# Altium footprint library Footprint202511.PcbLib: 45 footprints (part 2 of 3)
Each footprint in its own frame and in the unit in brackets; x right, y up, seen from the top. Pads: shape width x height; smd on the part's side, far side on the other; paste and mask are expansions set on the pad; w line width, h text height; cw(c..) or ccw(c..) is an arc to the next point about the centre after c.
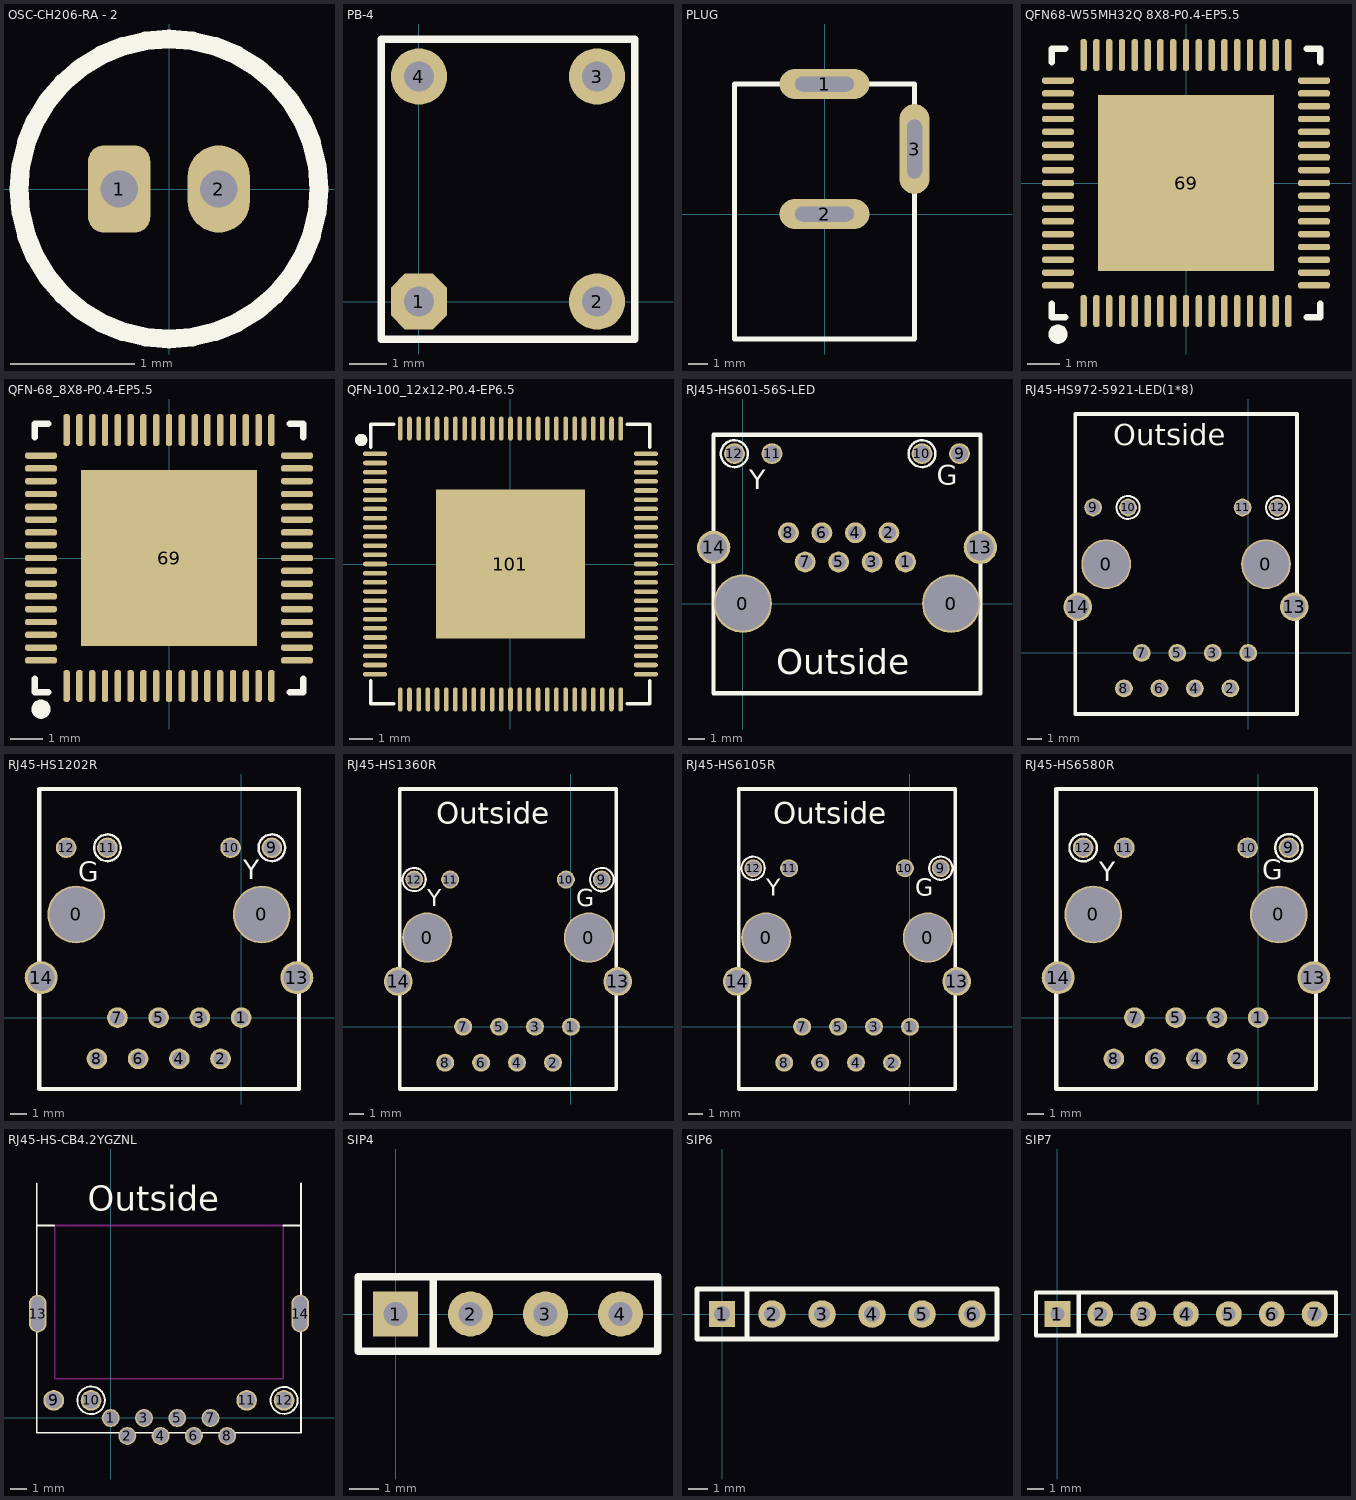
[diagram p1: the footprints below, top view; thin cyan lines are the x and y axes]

## OSC-CH206-RA - 2 [mm]
height 3.9
pads (2):
  rrect50% 0.5x0.7 hole 0.3: 1(-0.4,0)
  oval 0.5x0.7 hole 0.3: 2(0.4,0)
Top Overlay:
  circle w0.15: c0,0 r1.205

## PB-4 [mil]
height 21.65
pads (4):
  oct 60x60 hole 32: 1(0,0)
  round 60 hole 32: 2(190,0) 3(190,240) 4(0,240)
Top Overlay:
  lines w8: -40,-40 230,-40 230,280 -40,280 -40,-40

## PLUG [mil]
pads (3):
  oval 180x60 hole 30 slot 118.11 at 0 deg: 1(0,260) 2(0,0)
  oval 60x180 hole 30 slot 118.11 at 90 deg: 3(180,130)
Top Overlay:
  lines w10: -180,-250 180,-250 180,260 -180,260 -180,-250

## QFN68-W55MH32Q 8X8-P0.4-EP5.5 [mm]
height 1.45
pads (69):
  rrect80% 0.2x1 smd mask+0.051: 1(-3.2,-4) 2(-2.8,-4) 3(-2.4,-4) 4(-2,-4) 5(-1.6,-4) 6(-1.2,-4) 7(-0.8,-4) 8(-0.4,-4) 9(0,-4) 10(0.4,-4) 11(0.8,-4) 12(1.2,-4) 13(1.6,-4) 14(2,-4) 15(2.4,-4) 16(2.8,-4) 17(3.2,-4) 35(3.2,4) 36(2.8,4) 37(2.4,4) 38(2,4) 39(1.6,4) 40(1.2,4) 41(0.8,4) 42(0.4,4) 43(0,4) 44(-0.4,4) 45(-0.8,4) 46(-1.2,4) 47(-1.6,4) 48(-2,4) 49(-2.4,4) 50(-2.8,4) 51(-3.2,4)
  rrect80% 1x0.2 smd mask+0.051: 18(4,-3.2) 19(4,-2.8) 20(4,-2.4) 21(4,-2) 22(4,-1.6) 23(4,-1.2) 24(4,-0.8) 25(4,-0.4) 26(4,0) 27(4,0.4) 28(4,0.8) 29(4,1.2) 30(4,1.6) 31(4,2) 32(4,2.4) 33(4,2.8) 34(4,3.2) 52(-4,3.2) 53(-4,2.8) 54(-4,2.4) 55(-4,2) 56(-4,1.6) 57(-4,1.2) 58(-4,0.8) 59(-4,0.4) 60(-4,0) 61(-4,-0.4) 62(-4,-0.8) 63(-4,-1.2) 64(-4,-1.6) 65(-4,-2) 66(-4,-2.4) 67(-4,-2.8) 68(-4,-3.2)
  rect 5.5x5.5 smd paste-100 mask+0.051: 69(0,0)
Top Overlay:
  lines w0.2: -4.2,-3.775 -4.2,-4.2 -3.775,-4.2 ; -4.2,3.775 -4.2,4.2 -3.775,4.2 ; 3.775,-4.2 4.2,-4.2 4.2,-3.775 ; 3.775,4.2 4.2,4.2 4.2,3.775
  lines w0.3: -4,-4.575 ccw(c-3.999,-4.725) -3.999,-4.875 ccw(c-3.999,-4.725) -3.998,-4.575
3D body: height 1.05, standoff 0, extent -7.999,-7.999 8.001,8.001

## QFN-68_8X8-P0.4-EP5.5 [mm]
pads (69):
  rrect80% 0.2x1 smd mask+0.051: 1(-3.2,-4) 2(-2.8,-4) 3(-2.4,-4) 4(-2,-4) 5(-1.6,-4) 6(-1.2,-4) 7(-0.8,-4) 8(-0.4,-4) 9(0,-4) 10(0.4,-4) 11(0.8,-4) 12(1.2,-4) 13(1.6,-4) 14(2,-4) 15(2.4,-4) 16(2.8,-4) 17(3.2,-4) 35(3.2,4) 36(2.8,4) 37(2.4,4) 38(2,4) 39(1.6,4) 40(1.2,4) 41(0.8,4) 42(0.4,4) 43(0,4) 44(-0.4,4) 45(-0.8,4) 46(-1.2,4) 47(-1.6,4) 48(-2,4) 49(-2.4,4) 50(-2.8,4) 51(-3.2,4)
  rrect80% 1x0.2 smd mask+0.051: 18(4,-3.2) 19(4,-2.8) 20(4,-2.4) 21(4,-2) 22(4,-1.6) 23(4,-1.2) 24(4,-0.8) 25(4,-0.4) 26(4,0) 27(4,0.4) 28(4,0.8) 29(4,1.2) 30(4,1.6) 31(4,2) 32(4,2.4) 33(4,2.8) 34(4,3.2) 52(-4,3.2) 53(-4,2.8) 54(-4,2.4) 55(-4,2) 56(-4,1.6) 57(-4,1.2) 58(-4,0.8) 59(-4,0.4) 60(-4,0) 61(-4,-0.4) 62(-4,-0.8) 63(-4,-1.2) 64(-4,-1.6) 65(-4,-2) 66(-4,-2.4) 67(-4,-2.8) 68(-4,-3.2)
  rect 5.5x5.5 smd paste-100 mask+0.051: 69(0,0)
Top Overlay:
  lines w0.2: -4.2,-3.775 -4.2,-4.2 -3.775,-4.2 ; -4.2,3.775 -4.2,4.2 -3.775,4.2 ; 3.775,-4.2 4.2,-4.2 4.2,-3.775 ; 3.775,4.2 4.2,4.2 4.2,3.775
  lines w0.3: -4,-4.575 ccw(c-3.999,-4.725) -3.999,-4.875 ccw(c-3.999,-4.725) -3.998,-4.575
3D body: height 1.05, standoff 0, extent -7.999,-7.999 8.001,8.001

## QFN-100_12x12-P0.4-EP6.5 [mm]
pads (101):
  oval 1.05x0.2 smd mask+0.051: 1(-5.9,4.8) 2(-5.9,4.4) 3(-5.9,4) 4(-5.9,3.6) 5(-5.9,3.2) 6(-5.9,2.8) 7(-5.9,2.4) 8(-5.9,2) 9(-5.9,1.6) 10(-5.9,1.2) 11(-5.9,0.8) 12(-5.9,0.4) 13(-5.9,0) 14(-5.9,-0.4) 15(-5.9,-0.8) 16(-5.9,-1.2) 17(-5.9,-1.6) 18(-5.9,-2) 19(-5.9,-2.4) 20(-5.9,-2.8) 21(-5.9,-3.2) 22(-5.9,-3.6) 23(-5.9,-4) 24(-5.9,-4.4) 25(-5.9,-4.8) 51(5.9,-4.8) 52(5.9,-4.4) 53(5.9,-4) 54(5.9,-3.6) 55(5.9,-3.2) 56(5.9,-2.8) 57(5.9,-2.4) 58(5.9,-2) 59(5.9,-1.6) 60(5.9,-1.2) 61(5.9,-0.8) 62(5.9,-0.4) 63(5.9,0) 64(5.9,0.4) 65(5.9,0.8) 66(5.9,1.2) 67(5.9,1.6) 68(5.9,2) 69(5.9,2.4) 70(5.9,2.8) 71(5.9,3.2) 72(5.9,3.6) 73(5.9,4) 74(5.9,4.4) 75(5.9,4.8)
  oval 0.2x1.05 smd mask+0.051: 26(-4.8,-5.9) 27(-4.4,-5.9) 28(-4,-5.9) 29(-3.6,-5.9) 30(-3.2,-5.9) 31(-2.8,-5.9) 32(-2.4,-5.9) 33(-2,-5.9) 34(-1.6,-5.9) 35(-1.2,-5.9) 36(-0.8,-5.9) 37(-0.4,-5.9) 38(0,-5.9) 39(0.4,-5.9) 40(0.8,-5.9) 41(1.2,-5.9) 42(1.6,-5.9) 43(2,-5.9) 44(2.4,-5.9) 45(2.8,-5.9) 46(3.2,-5.9) 47(3.6,-5.9) 48(4,-5.9) 49(4.4,-5.9) 50(4.8,-5.9) 76(4.8,5.9) 77(4.4,5.9) 78(4,5.9) 79(3.6,5.9) 80(3.2,5.9) 81(2.8,5.9) 82(2.4,5.9) 83(2,5.9) 84(1.6,5.9) 85(1.2,5.9) 86(0.8,5.9) 87(0.4,5.9) 88(0,5.9) 89(-0.4,5.9) 90(-0.8,5.9) 91(-1.2,5.9) 92(-1.6,5.9) 93(-2,5.9) 94(-2.4,5.9) 95(-2.8,5.9) 96(-3.2,5.9) 97(-3.6,5.9) 98(-4,5.9) 99(-4.4,5.9) 100(-4.8,5.9)
  rect 6.5x6.5 smd mask+0.051: 101(0,0)
Top Overlay:
  circle w0.254: c-6.5,5.4 r0.141
  lines w0.152: -6.076,-5.076 -6.076,-6.076 -5.076,-6.076 ; -6.076,5.076 -6.076,6.076 -5.076,6.076 ; 5.076,-6.076 6.076,-6.076 6.076,-5.076 ; 5.076,6.076 6.076,6.076 6.076,5.076
3D body: height 0.9, standoff 0, extent -6,-6 6.02,6.02

## RJ45-HS601-56S-LED [mm]
height 13.2
pads (16):
  round 3.556 hole 3.302: 0(0,0) 0(12.7,0)
  round 1.27 hole 0.889: 1(9.92,2.54) 2(8.9,4.32) 3(7.88,2.54) 4(6.86,4.32) 5(5.84,2.54) 6(4.82,4.32) 7(3.8,2.54) 8(2.78,4.32)
  round 1.27 hole 1.016: 9(13.21,9.14) 10(10.92,9.14) 11(1.78,9.14) 12(-0.51,9.14)
  round 2.032 hole 1.626: 13(14.475,3.43)
  round 2.032 hole 1.651: 14(-1.775,3.43)
Top Overlay:
  circle w0.15: c-0.514,9.14 r0.82
  circle w0.15: c10.92,9.14 r0.82
  lines w0.254: -1.78,-5.46 14.48,-5.46 14.48,10.29 -1.78,10.29 -1.78,-5.46
  text "Y" at 0.381,6.985 h1.2
  text "G" at 11.811,7.239 h1.2
  text "Outside" at 2.032,-4.318 h1.52

## RJ45-HS972-5921-LED(1*8) [mil]
height 537.8
pads (16):
  round 140 hole 130: 0(-400,250) 0(50,250)
  round 50 hole 35: 1(0,0) 2(-50,-100) 3(-100,0) 4(-150,-100) 5(-200,0) 6(-250,-100) 7(-300,0) 8(-350,-100)
  round 50 hole 40: 9(-437.01,409.84) 10(-338.58,409.84) 11(-15.75,409.84) 12(82.68,409.84)
  round 80 hole 64: 13(129.92,129.92)
  round 80 hole 65: 14(-480.31,129.92)
Top Overlay:
  circle w5.91: c-338.58,409.84 r32.28
  circle w5.91: c82.68,409.84 r32.28
  lines w10: -487.6,-172.05 137.6,-172.05 ; -487.6,-171.26 -487.6,673.23 137.6,673.23 137.6,-171.26
  text "Outside" at -380,585 h60

## RJ45-HS1202R [mil]
height 633.46
pads (16):
  round 140 hole 130: 0(-400,250) 0(50,250)
  round 50 hole 35: 1(0,0) 2(-50,-100) 3(-100,0) 4(-150,-100) 5(-200,0) 6(-250,-100) 7(-300,0) 8(-350,-100)
  round 50 hole 40: 9(74.41,411.81) 10(-25.59,411.81) 11(-324.41,411.81) 12(-424.41,411.81)
  round 80 hole 64: 13(135.04,96.85)
  round 80 hole 65: 14(-485.04,96.85)
Top Overlay:
  circle w5.91: c74.41,411.81 r32.3
  circle w5.91: c-324.41,411.81 r32.28
  lines w10: -489.76,-173.23 -489.76,554.33 140.16,554.33 140.16,-173.23 -489.76,-173.23
  text "Y" at 5,335 h47.24
  text "G" at -395,330 h47.24

## RJ45-HS1360R [mil]
height 537.8
pads (16):
  round 140 hole 130: 0(-400,248.03) 0(50,248.03)
  round 50 hole 35: 1(0,0) 2(-50,-100) 3(-100,0) 4(-150,-100) 5(-200,0) 6(-250,-100) 7(-300,0) 8(-350,-100)
  round 50 hole 40: 9(85.83,409.45) 10(-14.17,409.45) 11(-336.22,409.45) 12(-436.22,409.45)
  round 80 hole 64: 13(129.92,125.98)
  round 80 hole 65: 14(-480.31,125.98)
Top Overlay:
  circle w5.91: c-436.22,409.45 r32.28
  circle w5.91: c85.83,409.45 r32.68
  lines w10: -476.38,-173.23 -476.38,661.42 125.98,661.42 125.98,-173.23 -476.38,-173.23
  text "Outside" at -375,565 h60
  text "Y" at -400,335 h47.24
  text "G" at 15,335 h47.24

## RJ45-HS6105R [mil]
height 537.8
pads (16):
  round 140 hole 130: 0(-400,248.03) 0(50,248.03)
  round 50 hole 35: 1(0,0) 2(-50,-100) 3(-100,0) 4(-150,-100) 5(-200,0) 6(-250,-100) 7(-300,0) 8(-350,-100)
  round 50 hole 40: 9(85.83,440.94) 10(-14.17,440.94) 11(-336.22,440.94) 12(-436.22,440.94)
  round 80 hole 64: 13(129.92,125.98)
  round 80 hole 65: 14(-480.31,125.98)
Top Overlay:
  circle w5.91: c-436.22,440.94 r32.28
  circle w5.91: c85.83,440.94 r32.28
  lines w10: -476.38,-173.23 -476.38,661.42 125.98,661.42 125.98,-173.23 -476.38,-173.23
  text "Y" at -400,365 h47.24
  text "G" at 15,365 h47.24
  text "Outside" at -380,565 h60

## RJ45-HS6580R [mil]
height 633.46
pads (16):
  round 140 hole 130: 0(-400,250) 0(50,250)
  round 50 hole 35: 1(0,0) 2(-50,-100) 3(-100,0) 4(-150,-100) 5(-200,0) 6(-250,-100) 7(-300,0) 8(-350,-100)
  round 50 hole 40: 9(74.41,411.81) 10(-25.59,411.81) 11(-324.41,411.81) 12(-424.41,411.81)
  round 80 hole 64: 13(135.04,96.85)
  round 80 hole 65: 14(-485.04,96.85)
Top Overlay:
  circle w5.91: c-424.41,411.81 r33.17
  circle w5.91: c74.41,411.81 r33.17
  lines w10: -489.76,-173.23 -489.76,554.33 140.16,554.33 140.16,-173.23 -489.76,-173.23
  text "G" at 10,335 h47.24
  text "Y" at -385,330 h47.24

## RJ45-HS-CB4.2YGZNL [mm]
height 11.05
pads (14):
  round 1.1 hole 0.9: 1(0,0) 2(1.02,-1.1) 3(2.04,0) 4(3.06,-1.1) 5(4.08,0) 6(5.1,-1.1) 7(6.12,0) 8(7.14,-1.1)
  round 1.27 hole 1: 9(-3.49,1.08) 10(-1.2,1.08) 11(8.34,1.08) 12(10.63,1.08)
  oval 1.1x2.3 hole 0.8 slot 2.1 at 90 deg: 13(-4.47,6.4) 14(11.62,6.4)
Top Overlay:
  circle w0.12: c-1.2,1.08 r0.846
  circle w0.12: c10.63,1.08 r0.827
  lines w0.1: -4.53,11.8 -3.465,11.8 ; -4.53,14.4 -4.53,-0.9 11.67,-0.9 11.67,14.4 ; 10.57,11.8 11.67,11.8
  text "Outside" at -1.397,12.7 h1.52
Keep-Out Layer:
  lines w0.1: -3.43,2.4 -3.43,11.8 10.57,11.8 10.57,2.4 -3.43,2.4

## SIP4 [mil]
height 43.31
pads (4):
  rect 60x60 hole 32 unplated: 1(0,0)
  round 60 hole 32 unplated: 2(100,0) 3(200,0) 4(300,0)
Top Overlay:
  lines w10: 50,-50 50,50 ; -50,-50 -50,50 350,50 350,-50 -50,-50

## SIP6 [mil]
height 43.31
pads (6):
  rect 51.06x51.06 hole 32: 1(0,0)
  round 55 hole 32: 2(100,0) 3(200,0) 4(300,0) 5(400,0) 6(500,0)
Top Overlay:
  lines w10: 50,-50 50,50 ; -50,-50 550,-50 550,50 -50,50 -50,-50

## SIP7 [mil]
pads (7):
  rect 60x60 hole 32: 1(0,0)
  round 60 hole 32: 2(100,0) 3(200,0) 4(300,0) 5(400,0) 6(500,0) 7(600,0)
Top Overlay:
  lines w10: 50,-50 50,50 ; 650,-50 -50,-50 -50,50 650,50 650,-45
